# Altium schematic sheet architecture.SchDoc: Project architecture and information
size A4; Organization: UFSC; DocumentNumber: 1; SheetNumber: 1; SheetTotal: 8
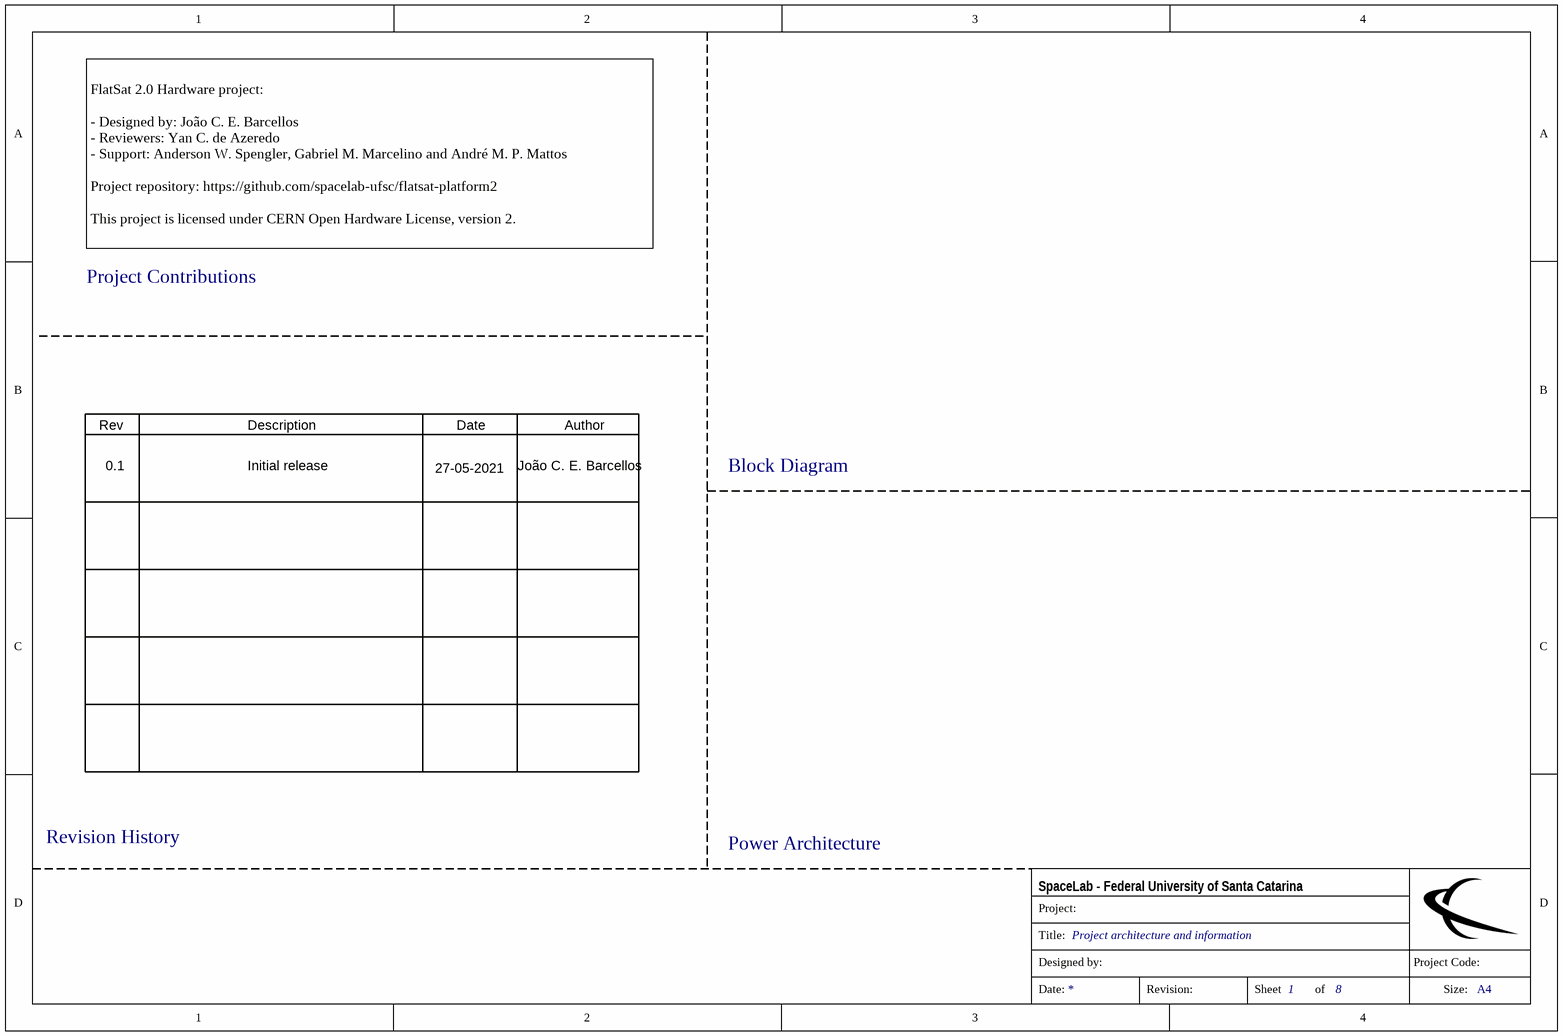
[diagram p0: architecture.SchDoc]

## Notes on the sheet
- FlatSat 2.0 Hardware project:
  - Designed by: João C. E. Barcellos
  - Reviewers: Yan C. de Azeredo
  - Support: Anderson W. Spengler, Gabriel M. Marcelino and André M. P. Mattos
  Project repository: https://github.com/spacelab-ufsc/flatsat-platform2
  This project is licensed under CERN Open Hardware License, version 2.
- Project Contributions
- Rev
- Description
- Date
- Author
- 0.1
- Initial release
- 27-05-2021
- João C. E. Barcellos
- Block Diagram
- Revision History
- Power Architecture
